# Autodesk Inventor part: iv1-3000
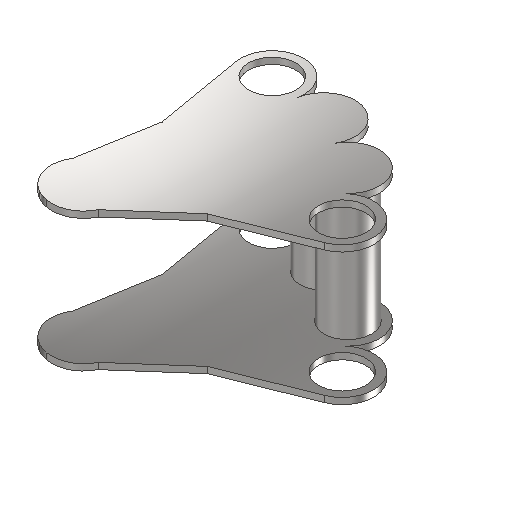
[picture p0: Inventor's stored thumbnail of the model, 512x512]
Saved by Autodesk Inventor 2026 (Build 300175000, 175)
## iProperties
Created: 2004-09
Part Number: iv1-3000
Document SubType Name: Modeling
Designer: Lars Bertram Pedersen
Manufacturer: Standard
Standards Organization: Custom
Material: Steel, Mild
Density: 7.85 g/cm^3
Appearance: Semi-Polished
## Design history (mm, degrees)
sketch "Sketch1"
  geometry: L1 (-25, 0)-(25, 0); L2 (-49.28, 141.547)-(-25, 0); L3 (49.28, 141.547)-(25, 0); C1 r 37.5 at (0, 150); A1 r 50 centre (0, 150) between (49.28, 141.547) and (-49.28, 141.547); 2 further points
  constraints: 6 end point, 2 centre point, 2 coincident, 2 point on circle, 2 tangent, 1 horizontal, 1 midpoint
  dimensions: "d0" = 75 diameter of C1; "d2" = 150 distance from line of L1 C1.centre; "d3" = 50 distance of L1.start L1.end; "d4" = 100 diameter of A1
extrude "Extrusion1" new body sketch "Sketch1" distance "d5" = 10; taper "d6" = 0 deg
mirror "Mirror1"
mirror "Mirror2"
mirror "Mirror3"
sketch "Sketch2"
  geometry: C1 r 37.5 at (185.852, 84.307) reference; C2 r 37.5 at (98.56, 133.093) reference
extrude "Extrusion2" join sketch "Sketch2" distance "d7" = 110; taper "d8" = 0 deg
mirror "Mirror4"
sketch "Sketch3"
  geometry: A1 r 37.5 centre (-2.675, -149.054) between (25.002, -123.752) and (16.245, -116.677) reference; A2 r 37.5 centre (-3.626, -147.973) between (-20.08, -181.671) and (25.002, -123.752) reference; A3 r 37.5 centre (0, -150) between (5.629, -112.925) and (-20.08, -181.671) reference; A4 r 37.5 centre (-1.419, -149.757) between (16.245, -116.677) and (5.629, -112.925) reference
extrude "Extrusion3" join sketch "Sketch3" distance "d9" = 10; taper "d10" = 0 deg
sketch "Sketch4"
  geometry: A1 r 37.5 centre (-1.419, -299.757) between (16.245, -266.677) and (5.629, -262.925) reference; A2 r 37.5 centre (-2.675, -299.054) between (25.002, -273.752) and (16.245, -266.677) reference; A3 r 37.5 centre (-3.626, -297.973) between (-20.08, -331.671) and (25.002, -273.752) reference; A4 r 37.5 centre (0, -300) between (5.629, -262.925) and (-20.08, -331.671) reference
extrude "Extrusion4" join sketch "Sketch4" distance "d11" = 10; taper "d12" = 0 deg
body "Solid1"
